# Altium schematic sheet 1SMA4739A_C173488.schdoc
size 127 x 101 mm
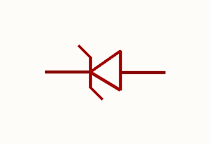
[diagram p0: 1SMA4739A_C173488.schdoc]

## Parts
D?  1sma4739a_c173488  [SMA_L4.3-W2.6-LS5.0-RD]  (value not drawn)

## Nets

Not connected (* = marked no-connect by the designer): D? 1 2

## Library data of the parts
D? = 1sma4739a_c173488: 二极管配置:1个独立式;稳压值(标称值):9.1V;稳压值(范围值):8.6V~9.59V;耗散功率(Pd):1W;; Manufacturer: MDD(辰达半导体); AddInBom: yes; ModelId: 8d2dd2e50a3a4b27821fa63d469a8f11; ModelTransform: 196.85,102.362,0,0,0,0,0,0,0; Diode Configuration: 1个独立式; Zener Voltage(Nom): 9.1V; Reverse Leakage Current (Ir): 10uA; Pd - Power Dissipation: 1W; Impedance(Zzt): 5Ω; Operating Junction Temperature Range: -55℃~+150℃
